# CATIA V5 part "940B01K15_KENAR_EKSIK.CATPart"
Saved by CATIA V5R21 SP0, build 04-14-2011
Part number: 940B01K15_KENAR_EKSIK
Bounding box of the stored display mesh (mm): x -8.5 to 161.962, y -7 to 7, z -25.901 to 9.099
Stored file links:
  C:\Users\ALI OZGUN\Desktop\alhan\940B01K15_KENAR_EKSIK.CATPart
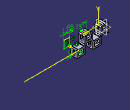
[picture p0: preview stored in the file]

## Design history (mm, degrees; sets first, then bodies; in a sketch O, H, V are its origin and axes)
Body1 (main body)
  Sketch1 on zx-plane, origin (0, 0, 0), H (-1, 0, 0), V (0, 0, 1)
    point P1 (-8.5, -8.9006)
    line L1 (-8.5, -7.9006) -> (-8, -7.4006)
    point P2 (-8, -7.4006)
    line L2 (-8, -7.4006) -> (-8, 6.6246)
    point P3 (-8, 6.6246)
    line L3 (-8, 6.6246) -> (-5.5251, 9.0994)
    point P4 (-5.5251, 9.0994)
    line L4 (-5.5251, 9.0994) -> (0, 9.0994)
    point P5 (0, 9.0994)
    line L5 (-8.5, -7.9006) -> (-8.5, -11.9006)
    point P6 (-8.5, -11.9006)
    line L6 (-8.5, -11.9006) -> (-5, -8.4006)
    point P7 (-3.5, -6.9006)
    line L7 (-5, -6.9006) -> (0, -6.9006)
    point P8 (0, -6.9006)
    line L8 (0, 6.2994) -> (-4.0825, 6.2994)
    point P9 (-4.0825, 6.2994)
    line L9 (-4.0825, 6.2994) -> (-5.2, 5.1819)
    point P10 (-5.2, 5.1819)
    line L10 (-5.2, 5.1819) -> (-5.2, -3.4006)
    point P11 (-5.2, -3.4006)
    line L11 (-5.2, -3.4006) -> (0, -3.4006)
    point P12 (0, -3.4006)
    point P13 (-8.5, -7.9006)
    point P14 (8, -7.4006)
    point P15 (8.5, -7.9006)
    line L12 (8.5, -7.9006) -> (8, -7.4006)
    point P16 (8, 6.6246)
    line L13 (8, -7.4006) -> (8, 6.6246)
    point P17 (5.5251, 9.0994)
    line L14 (8, 6.6246) -> (5.5251, 9.0994)
    point P18 (8.5, -11.9006)
    line L15 (8.5, -7.9006) -> (8.5, -11.9006)
    point P19 (3.5, -6.9006)
    line L16 (8.5, -11.9006) -> (5, -8.4006)
    point P20 (5.2, 5.1819)
    point P21 (4.0825, 6.2994)
    line L17 (4.0825, 6.2994) -> (5.2, 5.1819)
    point P22 (5.2, -3.4006)
    line L18 (5.2, 5.1819) -> (5.2, -3.4006)
    point P23 (0, -6.9006)
    line L19 (5, -6.9006) -> (0, -6.9006)
    point P24 (0, -3.4006)
    line L20 (5.2, -3.4006) -> (0, -3.4006)
    line L21 (0, 6.2994) -> (4.0825, 6.2994)
    point P25 (0, 9.0994)
    line L22 (5.5251, 9.0994) -> (0, 9.0994)
    point P26 (0, 6.2994)
    point P27 (0, 6.2994)
    line L23 (-5, -6.9006) -> (-5, -8.4006)
    line L24 (5, -6.9006) -> (5, -8.4006)
    distance L2 V = 8
    angle L3 L2 = 135
    distance L4 H = 9.0994
    distance L8 L4 = 2.8
    distance L10 L2 = 2.8
    distance L11 L7 = 3.5
    distance L9 L3 = 3
    length L3 = 3.5
    distance L4 L7 = 16
    distance L4 P6 = 21
    distance L5 L2 = 0.5
    length L5 = 4
    distance L23 L2 = 3
    vertical: L2 V, L5 V, L10 V, L23 V
    parallelism: L3 L1, L6 L1
    horizontal: L4 H, L7 H, L8 H, L11 H
    coincidence: P5 V, P8 V, P12 V, P1 L5, P26 V, P27 V, P5 P25, P8 P23, P12 P24, P26 P27, P7 L7, P7 L6, P19 L16, P19 L19
    symmetry: P2 P14 V, P13 P15 V, L1 L12 V, P3 P16 V, L2 L13 V, P4 P17 V, L3 L14 V, P6 P18 V, L5 L15 V, P7 P19 V, L6 L16 V, P10 P20 V, P9 P21 V, L9 L17 V, P11 P22 V, L10 L18 V, P8 P23 V, L7 L19 V, P12 P24 V, L11 L20 V, L8 L21 V, P5 P25 V, L4 L22 V, L23 L24 V
  Pad1: profile Sketch1, direction (0, 1, 0), length 7, mirrored extent
  Fillet1: radius 3, on edge [face of Pad1 from Sketch1.L22 | face of Pad1 from Sketch1.L14]; edge [face of Pad1 from Sketch1.L3 | face of Pad1 from Sketch1.L4]; edge [face of Pad1 from Sketch1.L2 | face of Pad1 from Sketch1.L3]; edge [face of Pad1 from Sketch1.L14 | face of Pad1 from Sketch1.L13]
  Fillet2: radius 1, on edge [face of Pad1 from Sketch1.L17 | face of Pad1 from Sketch1.L21]; edge [face of Pad1 from Sketch1.L18 | face of Pad1 from Sketch1.L17]; edge [face of Pad1 from Sketch1.L8 | face of Pad1 from Sketch1.L9]; edge [face of Pad1 from Sketch1.L9 | face of Pad1 from Sketch1.L10]
  Fillet3: radius 2, on edge [face of Pad1 from Sketch1.L23 | face of Pad1 from Sketch1.L6]; edge [face of Pad1 from Sketch1.L16 | face of Pad1 from Sketch1.L24]
  Fillet4: radius 1.5, on edge [face of Pad1 from Sketch1.L20 | face of Pad1 from Sketch1.L18]; edge [face of Pad1 from Sketch1.L10 | face of Pad1 from Sketch1.L11]
  Body2
    Sketch2 on zx-plane, origin (0, 0, 0), H (-1, 0, 0), V (0, 0, 1)
      line L1 (-8.5, -7.9006) -> (-10.5, -9.9006)
      line L2 (-10.5, -9.9006) -> (-17.3, -9.9006)
      line L3 (-8.5, -11.9006) -> (-9.05, -12.4506)
      line L4 (-9.05, -12.4506) -> (-9.05, -25.9006)
      line L5 (-9.05, -25.9006) -> (-17.3, -25.9006)
      line L6 (-17.3, -22.7006) -> (-11.85, -22.7006)
      line L7 (-11.85, -22.7006) -> (-11.85, -13.1006)
      line L8 (-11.85, -13.1006) -> (-17.3, -13.1006)
      axis line L9 (-17.3, -4.8689) -> (-17.3, -27.5881)
      point P6 (-17.3, -9.9006)
      point P7 (-17.3, -13.1006)
      point P8 (-17.3, -22.7006)
      point P9 (-17.3, -25.9006)
      reference projected line E1 (0, 9.0994) -> (-5.5251, 9.0994) from edge [face of Pad1 from Sketch1.L4 | end face of Pad1]
      reference projected line E2 (-8.5, -11.9006) -> (-5, -8.4006) from edge [face of Pad1 from Sketch1.L6 | end face of Pad1]
      reference projected line E3 (-8, -7.4006) -> (-8.5, -7.9006) from edge [face of Pad1 from Sketch1.L1 | end face of Pad1]
      projected line E4 (-8.5, -7.9006) -> (-8.5, -11.9006) from edge [face of Pad1 from Sketch1.L5 | end face of Pad1]
      projected line E5 (-8.5, -7.9006) -> (-8.5, -11.9006) from edge [face of Pad1 from Sketch1.L5 | end face of Pad1]
      reference projected line E6 (-8, 6.6246) -> (-8, -7.4006) from edge [face of Pad1 from Sketch1.L2 | end face of Pad1]
      line L10 (-17.3, -9.9006) -> (-17.3, -13.1006)
      line L11 (-17.3, -22.7006) -> (-17.3, -25.9006)
      distance L5 E1 = 35
      distance L2 L5 = 16
      distance L8 L2 = 3.2
      distance L6 L5 = 3.2
      distance L7 L4 = 2.8
      distance L4 E6 = 1.05
      distance L4 L9 = 8.25
      horizontal: L2 H, L5 H, L6 H, L8 H
      vertical: L4 V, L7 V, L9 V, L10 V, L11 V
      coincidence: P6 L9, P7 L9, P8 L9, P9 L9, L3 E2, L1 E3
    Pad2: profile Sketch2, direction (0, 1, 0), length 7, mirrored extent
    Mirror1: of the body so far, about face of Pad2 from Sketch2.L10
    Fillet5: radius 1.5, on edge [face of Pad2 | face of Mirror1] (x2); edge [face of Pad2 from Sketch2.L4 | face of Pad2]; edge [face of Mirror1 | face of Pad2] (x2); edge [face of Pad2 | face of Pad2 from Sketch2.L1]; edge [face of Pad2 from Sketch2.L7 | face of Pad2]; edge [face of Pad2 | face of Pad2 from Sketch2.L7]
  Add1: tool Body2
  RemoveFace1: RemoveFaces (face of Fillet5; face of Fillet1; face of Fillet5; face of Fillet1)
  Thickness1: Face (face of Pad2 from Sketch2.L4; face of Mirror1; face of Pad1 from Sketch1.L2; face of Pad1 from Sketch1.L13), Thickness 0.5
  RectPattern1: of the body so far, direction 1 instances 2, spacing 34.6, along edge [face of Pad1 | face of Pad2]
  Sketch3 on yz-plane, origin (0, 0, 0), H (0, 1, 0), V (0, 0, 1)
    construction line L1 (0, 4.5994) -> (0, -1.4006)
    point P1 (0, 4.5994)
    line L2 (2.5, 4.5994) -> (2.5, -1.4006)
    line L3 (-2.5, -1.4006) -> (-2.5, 4.5994)
    arc A1 centre (0, -1.4006) radius 2.5 from (2.5, -1.4006) to (-2.5, -1.4006) cw
    arc A2 centre (0, 4.5994) radius 2.5 from (-2.5, 4.5994) to (2.5, 4.5994) cw
    construction line L4 (0, -14.8006) -> (0, -20.8006)
    point P7 (0, -14.8006)
    point P8 (0, -20.8006)
    line L5 (2.5, -14.8006) -> (2.5, -20.8006)
    line L6 (-2.5, -20.8006) -> (-2.5, -14.8006)
    arc A3 centre (0, -20.8006) radius 2.5 from (2.5, -20.8006) to (-2.5, -20.8006) cw
    arc A4 centre (0, -14.8006) radius 2.5 from (-2.5, -14.8006) to (2.5, -14.8006) cw
    reference projected line E1 (-7, 9.0994) -> (7, 9.0994) from edge [face of Pad1 from Sketch1.L22 | face of Fillet1]
    distance L1 L2 = 2.5
    distance L4 L5 = 2.5
    length L1 = 6
    length L4 = 6
    distance A2 E1 = 2
    distance P8 P1 = 25.4
    coincidence: P1 V, P7 V
    vertical: L1 V, L4 V
    tangency: A1 L2, A2 L2, A1 L3, A2 L3, A3 L5, A4 L5, A3 L6, A4 L6
  Pocket1: profile Sketch3, direction (-1, 0, 0), through (limit type 3), opposite side through (limit type 3)
  Sketch4 on face of RectPattern1, origin (0, -7, 0), H (1, 0, 0), V (0, 0, 1)
    projected line E1 (43.15, -25.9006) -> (60.65, -25.9006) from edge [face of RectPattern1 | face of RectPattern1]
    projected line E2 (43.15, -25.9006) -> (161.9621, -25.9006) from edge [face of RectPattern1 | face of RectPattern1]
    projected line E3 (34.6, 9.0994) -> (38.8825, 9.0994) from edge [face of RectPattern1 | face of RectPattern1]
    projected line E4 (62.85, 9.0994) -> (75.35, 9.0994) from edge [face of RectPattern1 | face of RectPattern1]
    projected line E5 (60.7, -11.9006) -> (60.7, -7.9006) from edge [face of RectPattern1 | face of RectPattern1]
    projected line E6 (60.7, -11.9006) -> (60.7, -7.9006) from edge [face of RectPattern1 | face of RectPattern1]
    projected line E7 (60.7, -11.9006) -> (60.65, -11.9506) from edge [face of RectPattern1 | face of RectPattern1]
    projected line E8 (65.7, -6.9006) -> (60.7, -11.9006) from edge [face of RectPattern1 | face of RectPattern1]
    projected line E9 (60.7, -7.9006) -> (59.1393, -9.4612) from edge [face of RectPattern1 | face of RectPattern1]
    projected line E10 (62.85, -5.7506) -> (60.7, -7.9006) from edge [face of RectPattern1 | face of RectPattern1]
    line L1 (62.85, 9.0994) -> (62.85, -5.7506)
    line L2 (65.7, -6.9006) -> (75.35, -6.9006)
    line L3 (75.35, -6.9006) -> (75.35, 9.0994)
    reference projected line E11 (26.1, -7.9006) -> (26.1, 6.1246) from edge [face of RectPattern1 | face of RectPattern1]
    reference projected line E12 (60.65, -11.9506) -> (60.65, -25.9006) from edge [face of RectPattern1 | face of RectPattern1]
    reference projected line E13 (43.15, -11.9506) -> (43.15, -25.9006) from edge [face of RectPattern1 | face of RectPattern1]
    reference projected line E14 (34.6, -6.9006) -> (29.6, -6.9006) from edge [face of RectPattern1 | face of RectPattern1]
    distance L3 L1 = 12.5
    distance L3 E11 = 49.25
    distance E12 E13 = 17.5 (reference)
    vertical: L1 V, L3 V
    horizontal: L2 H
    coincidence: L2 E14
Body3
  Solid1: linked copy from another document
  Translate1: Direction xy-plane, Length 19.4, ToTransfor Solid1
